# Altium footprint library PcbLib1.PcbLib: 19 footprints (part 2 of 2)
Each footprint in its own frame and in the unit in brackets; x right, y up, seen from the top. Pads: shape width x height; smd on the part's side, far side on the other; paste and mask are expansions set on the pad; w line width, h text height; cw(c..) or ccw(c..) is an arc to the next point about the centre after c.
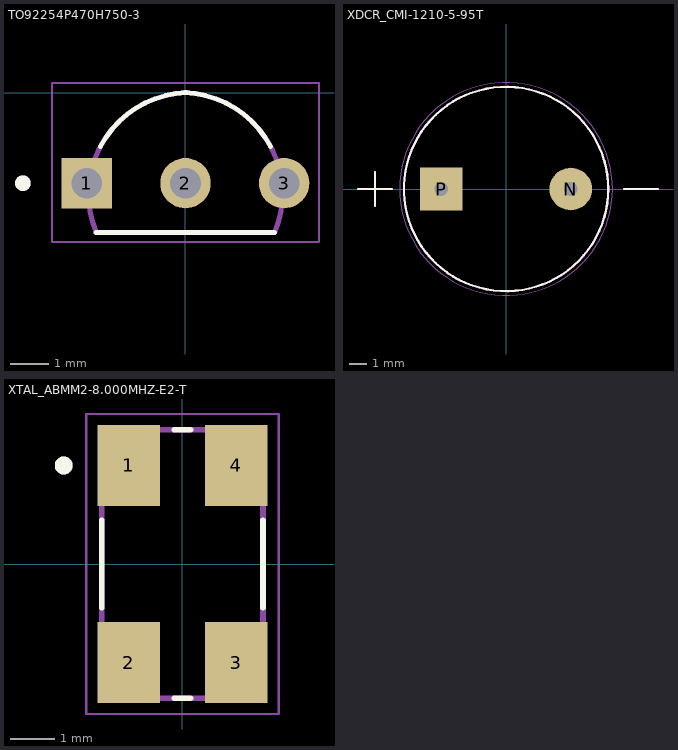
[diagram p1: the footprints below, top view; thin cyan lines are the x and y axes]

## TO92254P470H750-3 [mm]
height 7.5
pads (3):
  rect 1.298x1.298 / inner round 1.298 / far side rect 1.298x1.298 hole 0.79 mask+0.102: 1(-2.54,-2.33)
  round 1.298 hole 0.79 mask+0.102: 2(0,-2.33) 3(2.54,-2.33)
Top Overlay:
  circle w0.2: c-4.189,-2.33 r0.1
  lines w0.127: -2.3,-3.6 2.3,-3.6 ; -2.19,-1.381 cw(c0.112,-2.605) 0.021,0.001 ; -0.021,0.001 cw(c-0.112,-2.605) 2.19,-1.381
Mechanical 13:
  circle w0.2: c-4.189,-2.33 r0.1
  lines w0.127: -2.307,-3.582 cw(c0.11,-2.605) 0.019,0.001 ; -2.3,-3.6 2.3,-3.6 ; -0.019,0.001 cw(c-0.11,-2.605) 2.307,-3.582
Mechanical 15:
  lines w0.05: -3.439,-3.85 -3.439,0.252 3.439,0.252 3.439,-3.85 -3.439,-3.85
3D body "step_temp.STEP": height 8.09, standoff -9.01, extent -2.74,-3.6 2.74,0

## XDCR_CMI-1210-5-95T [mm]
height 10
pads (2):
  round 2.5 hole 0.8: N(3.8,0)
  rect 2.5x2.5 / inner round 2.5 / far side rect 2.5x2.5 hole 0.8: P(-3.8,0)
Top Overlay:
  circle w0.127: c0,0 r6
  lines w0.127: -8.69,0 -6.69,0 ; -7.69,-1 -7.69,1 ; 6.92,0 8.92,0
Mechanical 13:
  circle w0.127: c0,0 r6
  lines w0.127: -8.69,0 -6.69,0 ; -7.69,-1 -7.69,1 ; 6.92,0 8.92,0
Mechanical 15:
  circle w0.05: c0,0 r6.25
3D body "step_temp.STEP": height 7, standoff -7, extent -6,-6 6,6

## XTAL_ABMM2-8.000MHZ-E2-T [mm]
height 1.2
pads (4):
  rect 1.4x1.8 smd: 1(-1.2,2.2) 2(-1.2,-2.2) 3(1.2,-2.2) 4(1.2,2.2)
Top Overlay:
  circle w0.2: c-2.65,2.2 r0.1
  lines w0.127: -1.8,-0.98 -1.8,0.98 ; -0.18,-3 0.18,-3 ; -0.18,3 0.18,3 ; 1.8,-0.98 1.8,0.98
Mechanical 13:
  circle w0.2: c-2.65,2.2 r0.1
  lines w0.127: -1.8,-3 1.8,-3 1.8,3 -1.8,3 -1.8,-3
Mechanical 15:
  lines w0.05: -2.15,-3.35 2.15,-3.35 2.15,3.35 -2.15,3.35 -2.15,-3.35
3D body "step_temp.STEP": height 1.2, standoff 0, extent -1.778,-3 1.822,3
